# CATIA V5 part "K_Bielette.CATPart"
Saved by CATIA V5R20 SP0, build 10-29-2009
Part number: Bielette
Bounding box of the stored display mesh (mm): x -21 to 21, y 189.175 to 196.142, z 134.987 to 165.373
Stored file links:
  G:\Khaled_CFAO_2011\ST2M\ST2M_GR1\hgrenier\Khaled\CAD_ThinkMOTION\K_Bielette.CATPart
  C:\Users\Tom\Documents\Cours 2A\CFAO\Projet thinkmotion\Hugo\porte_outil.CATProduct
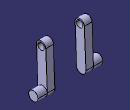
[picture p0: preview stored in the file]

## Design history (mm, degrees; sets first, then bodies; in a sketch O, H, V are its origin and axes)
Set1
  Plane1 "Plan_bielle2": linked copy from another document
  Point1 "Centre_bielle2/bielette": linked copy from another document
  Point2 "Centre_bielette/godet": linked copy from another document
  Plane2 "Plan_godet": linked copy from another document
  Plane3 "plan_sym": linked copy from another document
Body1 (main body)
  Sketch1 on Plane1, origin (15, 0, 0), H (0, 1, 0), V (0, 0, 1)
    construction line L1 (192.173, 162.375) -> (193.142, 137.987)
    point P1 (192.173, 162.375)
    point P2 (193.142, 137.987)
    line L2 (195.1706, 162.4941) -> (196.1396, 138.1061)
    line L3 (190.1444, 137.8679) -> (189.1754, 162.2559)
    arc A1 centre (193.142, 137.987) radius 3 from (196.1396, 138.1061) to (190.1444, 137.8679) cw
    arc A2 centre (192.173, 162.375) radius 3 from (189.1754, 162.2559) to (195.1706, 162.4941) cw
    reference projected point E1 (192.173, 162.375) from Point1
    reference projected point E2 (193.142, 137.987) from Point2
    circle A3 centre (192.173, 162.375) radius 2.1195
    point P7 (192.173, 162.375)
    reference projected point E3 (192.173, 162.375) from Point1
    distance L1 L2 = 3
    radius A3 = 2.1195
    tangency: A1 L2, A2 L2, A1 L3, A2 L3
    coincidence: P1 E1, E2 P2, P7 E3
  Pad1: profile Sketch1, direction (-1, 0, 0), length 5
  Sketch2 on start face of Pad1, origin (15, 0, 0), H (0, 1, 0), V (0, 0, 1)
    circle A1 centre (193.142, 137.987) radius 3
    point P1 (193.142, 137.987)
    reference projected point E1 (193.142, 137.987) from Point2
    radius A1 = 3
    coincidence: P1 E1
  Pad2: profile Sketch2, direction (1, 0, 0), up to Plane2
  Mirror1: of the body so far, about Plane3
